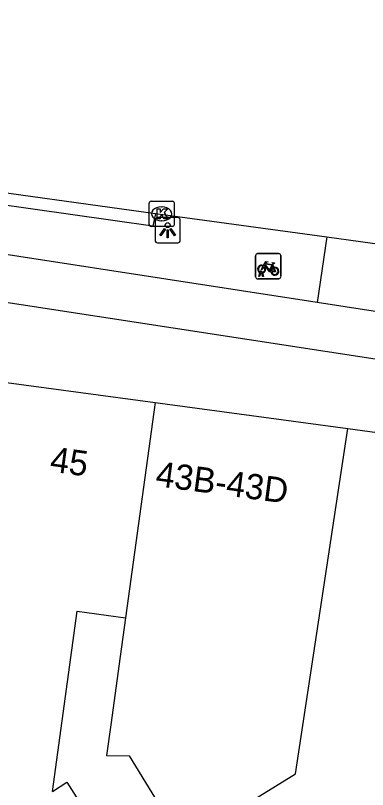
# Model space of a CAD drawing. Extents: x 160664 to 161506, y 382245 to 383288.
# Drawn here: x 160838.59 to 160852.57, y 383245.11 to 383275.84 of the extents above; entities that cross this region are included whole.
import ezdxf

# ---------------------------------------------------------------- set-up
doc = ezdxf.new("R2010")
doc.units = 0
for name, color, linetype in [('IMGEO_Berm_open', 7, 'Continuous'), ('IMGEO_Fietsenrek', 7, 'Continuous'), ('IMGEO_Fietspad_gesloten', 7, 'Continuous'), ('IMGEO_Kolk', 7, 'Continuous'), ('IMGEO_Lichtpunt', 7, 'Continuous'), ('IMGEO_Pand', 7, 'Continuous'), ('IMGEO_Pand_nummerreeks', 7, 'Continuous'), ('IMGEO_Rijbaan_lokaal_gesloten', 7, 'Continuous'), ('IMGEO_Voetpad_open', 7, 'Continuous')]:
    doc.layers.add(name, color=color, linetype=linetype)

msp = doc.modelspace()

# ---------------------------------------------------------------- linework, layer by layer
at = {"layer": 'IMGEO_Berm_open'}
msp.add_lwpolyline([(160850.949, 383267.047), (160850.573, 383264.439)], dxfattribs=at)
at = {"layer": 'IMGEO_Fietsenrek'}
for p, q in [((160848.199, 383266.385), (160849.04, 383266.385)), ((160849.04, 383266.385), (160848.199, 383266.385)), ((160848.124, 383265.46), (160848.124, 383266.301)), ((160848.124, 383266.301), (160848.124, 383265.46)), ((160849.124, 383266.31), (160849.124, 383265.469)), ((160849.124, 383265.469), (160849.124, 383266.31)), ((160848.811, 383265.934), (160848.847, 383265.839)), ((160848.251, 383265.469), (160848.29, 383265.629)), ((160848.285, 383265.469), (160848.251, 383265.469)), ((160848.32, 383265.617), (160848.285, 383265.469)), ((160848.362, 383265.641), (160848.361, 383265.645)), ((160848.403, 383265.469), (160848.369, 383265.611)), ((160848.393, 383265.652), (160848.394, 383265.645)), ((160848.401, 383265.615), (160848.436, 383265.469)), ((160848.436, 383265.469), (160848.403, 383265.469)), ((160849.049, 383265.385), (160848.208, 383265.385)), ((160848.208, 383265.385), (160849.049, 383265.385))]:
    msp.add_line(p, q, dxfattribs=at)
for points in [[(160848.437, 383265.911), (160848.532, 383266.075), (160848.618, 383266.061), (160848.62, 383266.052), (160848.564, 383266.041), (160848.537, 383265.996), (160848.793, 383265.955)], [(160848.793, 383265.955), (160848.818, 383266.004), (160848.812, 383266.008), (160848.789, 383266.012), (160848.777, 383266.019), (160848.776, 383266.022), (160848.778, 383266.027), (160848.873, 383266.012), (160848.875, 383266.002), (160848.865, 383265.989), (160848.853, 383265.983), (160848.839, 383265.989), (160848.811, 383265.934)], [(160848.458, 383265.859), (160848.406, 383265.769), (160848.366, 383265.744), (160848.367, 383265.791), (160848.422, 383265.885)], [(160848.733, 383265.667), (160848.683, 383265.667), (160848.492, 383265.918), (160848.473, 383265.886)], [(160848.78, 383265.93), (160848.523, 383265.971), (160848.506, 383265.942), (160848.673, 383265.722), (160848.78, 383265.93)], [(160848.828, 383265.832), (160848.798, 383265.909), (160848.689, 383265.691), (160848.732, 383265.691)], [(160848.762, 383265.691), (160848.882, 383265.69), (160848.838, 383265.804)], [(160848.858, 383265.811), (160848.913, 383265.666), (160848.763, 383265.666)]]:
    msp.add_lwpolyline(points, dxfattribs=at)
for centre, radius, start, end in [((160848.202, 383266.307), 0.0779, 92.4484, 184.2845), ((160848.202, 383266.307), 0.0779, 92.4484, 184.2845), ((160849.046, 383266.307), 0.0779, 2.4484, 94.2845), ((160849.046, 383266.307), 0.0779, 2.4484, 94.2845), ((160848.364, 383265.77), 0.159, 62.6766, 242.1369), ((160848.364, 383265.77), 0.129, 63.3192, 238.903), ((160848.364, 383265.77), 0.129, 283.6043, 43.4302), ((160848.364, 383265.77), 0.159, 283.5766, 46.6042), ((160848.891, 383265.686), 0.159, 113.3408, 178.3217), ((160848.891, 383265.686), 0.159, 187.0065, 105.7708), ((160848.891, 383265.686), 0.129, 113.923, 177.9556), ((160848.891, 383265.686), 0.129, 188.6715, 104.5883), ((160848.202, 383265.463), 0.0779, 182.4484, 274.2845), ((160848.202, 383265.463), 0.0779, 182.4484, 274.2845), ((160848.344, 383265.641), 0.0499, 12.8025, 158.6934), ((160848.364, 383265.77), 0.159, 253.9967, 271.7867), ((160848.344, 383265.641), 0.0174, 12.8025, 163.4502), ((160848.364, 383265.77), 0.129, 253.415, 269.0204), ((160849.046, 383265.463), 0.0779, 272.4484, 4.2845), ((160849.046, 383265.463), 0.0779, 272.4484, 4.2845)]:
    msp.add_arc(centre, radius, start, end, dxfattribs=at)
at = {"layer": 'IMGEO_Fietspad_gesloten'}
for points in [[(160749.571, 383275.838), (160772.375, 383273.271), (160826.897, 383266.189), (160865.807, 383260.226)], [(160850.573, 383264.439), (160832.69, 383267.191)], [(160855.96, 383263.61), (160850.573, 383264.439)]]:
    msp.add_lwpolyline(points, dxfattribs=at)
at = {"layer": 'IMGEO_Kolk'}
for p, q in [((160843.896, 383267.538), (160843.896, 383268.39)), ((160843.971, 383268.464), (160844.823, 383268.464)), ((160844.384, 383268.244), (160844.409, 383268.244)), ((160844.897, 383268.39), (160844.897, 383267.538)), ((160844.407, 383267.684), (160844.382, 383267.684)), ((160844.823, 383267.464), (160843.971, 383267.464))]:
    msp.add_line(p, q, dxfattribs=at)
for points in [[(160843.896, 383267.538), (160843.896, 383268.39)], [(160843.971, 383268.464), (160844.823, 383268.464)], [(160844.217, 383268.164), (160844.34, 383268.164), (160844.34, 383268.013), (160844.47, 383268.164), (160844.634, 383268.164), (160844.488, 383268.013), (160844.641, 383267.764), (160844.489, 383267.764), (160844.404, 383267.928), (160844.34, 383267.861), (160844.34, 383267.764), (160844.217, 383267.764), (160844.217, 383268.164)], [(160844.897, 383268.39), (160844.897, 383267.538)], [(160844.823, 383267.464), (160843.971, 383267.464)]]:
    msp.add_lwpolyline(points, dxfattribs=at)
for centre, start, end in [((160843.973, 383268.388), 91.552, 178.448), ((160843.973, 383268.388), 91.552, 178.448), ((160844.821, 383268.388), 1.552, 88.448), ((160844.821, 383268.388), 1.552, 88.448), ((160843.973, 383267.54), 181.552, 268.448), ((160843.973, 383267.54), 181.552, 268.448), ((160844.821, 383267.54), 271.552, 358.448), ((160844.821, 383267.54), 271.552, 358.448)]:
    msp.add_arc(centre, 0.0765, start, end, dxfattribs=at)
for centre, major_axis, ratio, start_param, end_param in [((160844.383, 383267.964), (-0.387, 0.002), 0.722429, 4.712389, 7.853982), ((160844.408, 383267.964), (-0.39, 0.002), 0.717154, 1.570796, 4.712389)]:
    msp.add_ellipse(centre, major_axis=major_axis, ratio=ratio, start_param=start_param, end_param=end_param, dxfattribs=at)
at = {"layer": 'IMGEO_Lichtpunt'}
for p, q in [((160844.134, 383267.717), (160844.134, 383266.91)), ((160844.134, 383267.717), (160844.134, 383266.91)), ((160845.036, 383267.812), (160844.228, 383267.812)), ((160845.036, 383267.812), (160844.228, 383267.812)), ((160845.13, 383266.91), (160845.13, 383267.717)), ((160845.13, 383266.91), (160845.13, 383267.717)), ((160844.228, 383266.816), (160845.036, 383266.816)), ((160844.228, 383266.816), (160845.036, 383266.816))]:
    msp.add_line(p, q, dxfattribs=at)
for points in [[(160844.508, 383267.381), (160844.547, 383267.353), (160844.359, 383267.091), (160844.321, 383267.118), (160844.508, 383267.381)], [(160844.61, 383267.333), (160844.657, 383267.333), (160844.657, 383267.011), (160844.61, 383267.011), (160844.61, 383267.333)], [(160844.72, 383267.353), (160844.758, 383267.38), (160844.945, 383267.118), (160844.906, 383267.09), (160844.72, 383267.353)]]:
    msp.add_lwpolyline(points, dxfattribs=at)
msp.add_circle((160844.633, 383267.515), 0.0994, dxfattribs=at)
for centre, start, end in [((160844.228, 383267.717), 90, 180), ((160844.228, 383267.717), 90, 180), ((160845.036, 383267.717), 0, 90), ((160845.036, 383267.717), 0, 90), ((160844.228, 383266.91), 180, 270), ((160844.228, 383266.91), 180, 270), ((160845.036, 383266.91), 270, 0), ((160845.036, 383266.91), 270, 360)]:
    msp.add_arc(centre, 0.0946, start, end, dxfattribs=at)
at = {"layer": 'IMGEO_Pand'}
for points in [[(160838.231, 383261.273), (160844.135, 383260.477)], [(160844.135, 383260.477), (160842.958, 383251.922)], [(160844.135, 383260.477), (160851.794, 383259.444)], [(160846.088, 383243.501), (160849.714, 383245.736), (160850.361, 383250), (160851.794, 383259.444)], [(160851.794, 383259.444), (160860.248, 383258.284)], [(160840.056, 383245.035), (160841.04, 383252.186), (160842.958, 383251.922)], [(160842.958, 383251.922), (160842.694, 383250), (160842.386, 383247.767), (160842.206, 383246.455), (160843.103, 383246.441), (160845.156, 383243.103), (160846, 383243.639), (160846.088, 383243.501)], [(160840.056, 383245.035), (160840.631, 383245.402), (160844.626, 383239.108), (160846.723, 383240.441), (160848.945, 383236.939), (160851.624, 383232.717)]]:
    msp.add_lwpolyline(points, dxfattribs=at)
at = {"layer": 'IMGEO_Rijbaan_lokaal_gesloten'}
for points in [[(160832.959, 383269.529), (160844.144, 383267.979)], [(160844.144, 383267.979), (160850.949, 383267.047)], [(160850.949, 383267.047), (160856.311, 383266.312)]]:
    msp.add_lwpolyline(points, dxfattribs=at)
at = {"layer": 'IMGEO_Voetpad_open'}
msp.add_lwpolyline([(160844.144, 383267.979), (160844.049, 383267.473), (160832.907, 383269.052)], dxfattribs=at)

# ---------------------------------------------------------------- texts
at = {"layer": 'IMGEO_Pand_nummerreeks'}
for s, rotation, p in [('45', 352.2536, (160839.923, 383257.738)), ('43B-43D', 352.3854, (160844.118, 383257.159))]:
    msp.add_text(s, height=1, rotation=rotation, dxfattribs=at).set_placement(p)

doc.saveas('drawing.dxf')
